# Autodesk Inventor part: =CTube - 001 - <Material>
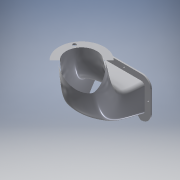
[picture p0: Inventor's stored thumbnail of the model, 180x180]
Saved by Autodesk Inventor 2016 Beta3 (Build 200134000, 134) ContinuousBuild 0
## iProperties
Created: 2006-10
Part Number: =CTube - 001 - <Material>
Document SubType Name: Modeling
Designer: Autodesk, Inc.
Density: 2.71 g/cm^3
Material: Aluminum-6061
Description: Exhaust Tube - Transitional
Mass: 16972.7 g
Surface Area: 12672.8 cm^2
Volume: 6263 cm^3
Appearance: Aluminum - Flat
Author: Autodesk, Inc.
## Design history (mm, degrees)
node "Distance Plane"
sketch "Sketch2"
  geometry: L1 (-78.628, 403.823)-(-78.628, 548.123); L2 (-78.628, 403.823)-(46.339, 331.673); L3 (-78.628, 403.823)-(-203.596, 331.673); C1 r 114.3 at (-78.628, 403.823); C2 r 169.3 at (-78.628, 403.823); C3 r 12.7 at (-78.628, 548.123); C4 r 12.7 at (46.339, 331.673); C5 r 12.7 at (-203.596, 331.673); A1 r 144.3 centre (-78.628, 403.823) between (-78.628, 548.123) and (46.339, 331.673); 1 further point
  constraints: 6 centre point, 6 end point, 3 point on circle, 2 coincident, 2 equal radius, 1 vertical
  dimensions: "d22" = 228.6 diameter of C1; "d23" = 338.6 diameter of C2 (computed from d22); "d24" = 288.6 diameter of A1 (computed from d22); "d88" = 120 deg angle of L3 L1; "d89" = 120 deg angle of L2 L1 (= d88); "d113" = 25.4 diameter of C3
node "Angle Plane"
  workaxis "Work Axis1"
feature "Stitch Surface4" dims "d138" = 0.254 (derived)
thicken "Thicken4" dims "d137" = 10.16
body "Solid1"
sketch "3D Sketch3" dims "d14" = 25.4, "d15" = 25.4
body "Srf2"
body "Srf3"
body "Srf1"
body "Srf4"
patch "Boundary Patch1"
patch "Boundary Patch2"
feature "LoftSrf4" dims "d115" = 0, "d116" = 90 deg, "d117" = 0, "d118" = 90 deg, "d119" = 0, "d120" = 90 deg, "d121" = 0, "d122" = 0, "d123" = 4042.21261, "d124" = 10.00133, "d125" = 660.87569, "d126" = 10, "d127" = 5491.09151, "d128" = 10.00086, "d129" = 453.91524, "d130" = 6.86839, "d131" = 3999.992, "d132" = 7.93428, "d133" = 257.666, "d134" = 3.89886, "d135" = 3999.992, "d136" = 8.66046
other parameters: "d2" = 406.4, "d26" = 10 deg, "d114" = 12.7
